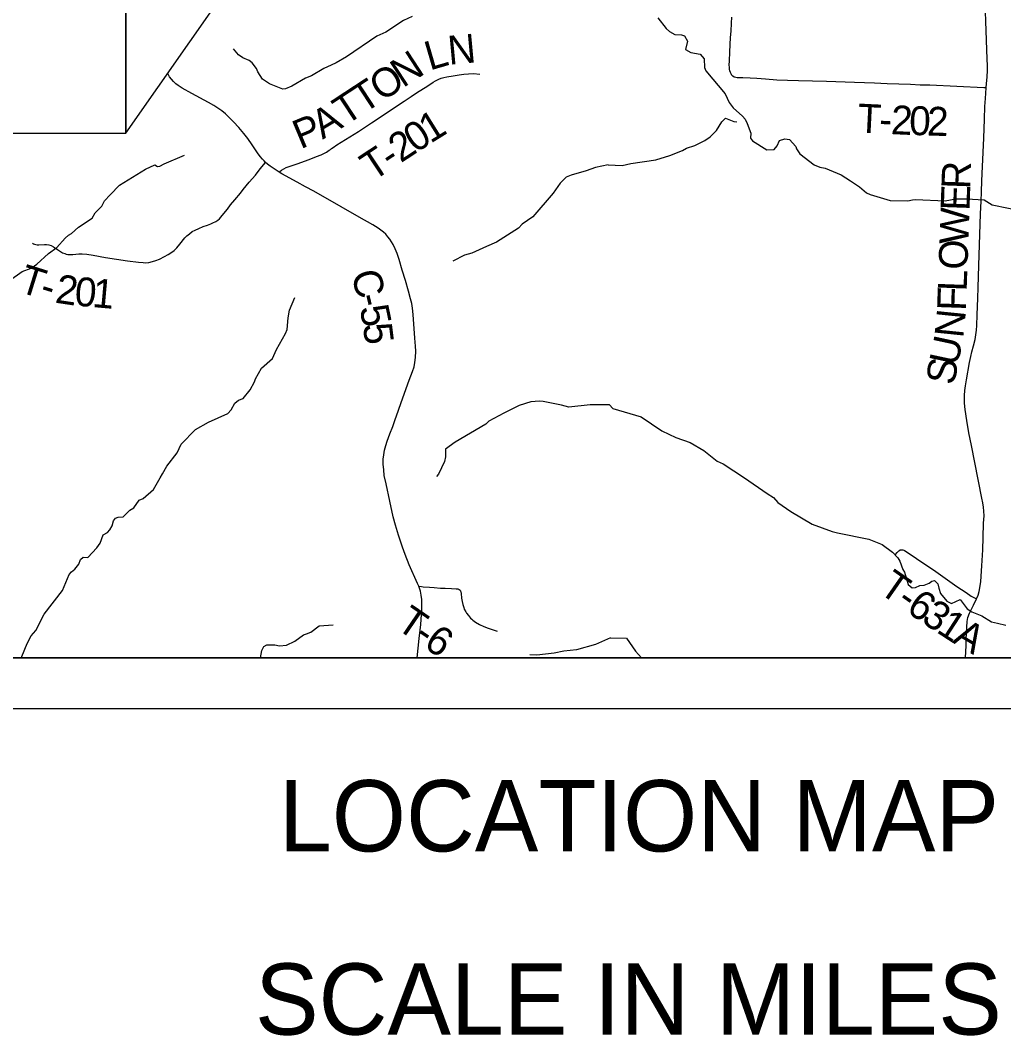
# Model space of a CAD drawing. Extents: x 0 to 34, y 0 to 22.
# Drawn here: x 26.169 to 28.101, y 13.358 to 15.353 of the extents above; entities that cross this region are included whole.
import ezdxf

# ---------------------------------------------------------------- set-up
doc = ezdxf.new("R2010")
doc.units = 0
for name, color, linetype in [('GM_X_Adjacent_County', 7, 'Continuous'), ('GM_X_County', 7, 'Continuous'), ('GM_X_County_Road', 7, 'Continuous'), ('GM_X_County_Road_Text', 7, 'Continuous'), ('GM_X_Minor_River', 7, 'Continuous'), ('GM_X_Township', 7, 'Continuous'), ('GM_X_Township_Road', 7, 'Continuous'), ('GM_X_Township_Road_Text', 7, 'Continuous'), ('SH_Data', 7, 'Continuous'), ('SH_Text', 7, 'Continuous')]:
    doc.layers.add(name, color=color, linetype=linetype)

msp = doc.modelspace()

# ---------------------------------------------------------------- linework, layer by layer
at = {"layer": 'GM_X_Adjacent_County'}
msp.add_lwpolyline([(28.7526, 20.9), (24.0167, 20.9), (24.0167, 14.1), (28.5181, 14.1)], dxfattribs=at)
at = {"layer": 'GM_X_County'}
msp.add_lwpolyline([(28.7526, 20.9), (24.0167, 20.9), (24.0167, 14.1), (28.5181, 14.1)], dxfattribs=at)
at = {"layer": 'GM_X_County_Road'}
for points in [[(28.0665, 15.2197), (28.0671, 15.2285), (28.0682, 15.241), (28.0688, 15.2543), (28.0688, 15.2639), (28.0682, 15.2763), (28.066, 15.3505), (28.0651, 15.3691)], [(26.651, 15.073), (26.6481, 15.0762), (26.6446, 15.08), (26.6406, 15.0849), (26.6352, 15.0923), (26.6248, 15.1076), (26.6158, 15.1202), (26.6081, 15.1299), (26.5981, 15.1417), (26.5877, 15.1533), (26.579, 15.1622), (26.5722, 15.1685), (26.5649, 15.1745), (26.5573, 15.1799), (26.5494, 15.1849), (26.5386, 15.1911), (26.5059, 15.2087), (26.487, 15.2193), (26.4793, 15.2242), (26.4744, 15.2279), (26.4699, 15.2321), (26.466, 15.2367), (26.4625, 15.2417), (26.4594, 15.247), (26.4588, 15.2483)], [(28.0475, 14.2159), (28.0507, 14.2234), (28.0529, 14.2307), (28.0542, 14.238), (28.0557, 14.2503), (28.058, 14.2812), (28.0597, 14.3121), (28.0608, 14.3369), (28.0615, 14.365), (28.0623, 14.3793), (28.062, 14.3885), (28.0615, 14.396), (28.0599, 14.4049), (28.0581, 14.4139), (28.0443, 14.4841), (28.0374, 14.5176), (28.0326, 14.542), (28.0284, 14.5664), (28.0254, 14.5879), (28.0241, 14.6003), (28.0238, 14.6096), (28.0239, 14.6158), (28.0247, 14.6251), (28.026, 14.6343), (28.0281, 14.6465), (28.0338, 14.6802), (28.0362, 14.6924), (28.0384, 14.7015), (28.0415, 14.7134), (28.0445, 14.7255), (28.046, 14.7347), (28.0472, 14.7439), (28.0479, 14.7532), (28.0485, 14.7741), (28.0499, 14.8068), (28.0509, 14.8275), (28.0523, 14.8712), (28.0555, 14.9723), (28.0564, 14.9971), (28.0571, 15.0157), (28.058, 15.0375), (28.0592, 15.0654), (28.0618, 15.1212), (28.0631, 15.1584), (28.0639, 15.1831), (28.0649, 15.1986), (28.0665, 15.2197)], [(26.6778, 15.0544), (26.6699, 15.0592), (26.6597, 15.0662), (26.655, 15.0697), (26.651, 15.073)], [(26.9518, 14.2408), (26.9495, 14.246), (26.9333, 14.283), (26.925, 14.3031), (26.9196, 14.3176), (26.9119, 14.3412), (26.9061, 14.3609), (26.9018, 14.3771), (26.8948, 14.4078), (26.8875, 14.4423), (26.8842, 14.4583), (26.8829, 14.4696), (26.8819, 14.4805), (26.8821, 14.4903), (26.8829, 14.4989), (26.8847, 14.508), (26.8871, 14.517), (26.8899, 14.5258), (26.8951, 14.5404), (26.9006, 14.5549), (26.9049, 14.5665), (26.9123, 14.587), (26.9175, 14.6017), (26.9332, 14.6455), (26.9398, 14.663), (26.9428, 14.6721), (26.9444, 14.6802), (26.9457, 14.6902), (26.946, 14.7023), (26.9454, 14.7126), (26.9444, 14.7281), (26.9408, 14.7746), (26.9395, 14.787), (26.9379, 14.7962), (26.9359, 14.8053), (26.9319, 14.8204), (26.9256, 14.8412), (26.9193, 14.862), (26.9131, 14.8828), (26.9091, 14.8947), (26.9056, 14.9034), (26.9017, 14.9119), (26.8986, 14.9174), (26.8951, 14.9226), (26.8912, 14.9275), (26.887, 14.9322), (26.8824, 14.9365), (26.8775, 14.9404), (26.8724, 14.9441), (26.8618, 14.9506), (26.8348, 14.966), (26.7997, 14.986), (26.7457, 15.0167), (26.7293, 15.0256), (26.7129, 15.0345), (26.6831, 15.0511), (26.6778, 15.0544)], [(26.9484, 14.1), (26.9529, 14.1381), (26.9556, 14.166), (26.9581, 14.1953), (26.9581, 14.2058), (26.9579, 14.215), (26.9568, 14.2236), (26.955, 14.2309), (26.9532, 14.2371), (26.9518, 14.2408)], [(28.0256, 14.1), (28.0269, 14.1246), (28.0271, 14.137), (28.0289, 14.1714), (28.0307, 14.1794), (28.034, 14.1878), (28.0369, 14.1946), (28.0418, 14.204), (28.0475, 14.2159)]]:
    msp.add_lwpolyline(points, dxfattribs=at)
at = {"layer": 'GM_X_Minor_River'}
for points in [[(26.9391, 15.3603), (26.9217, 15.3522), (26.887, 15.3289), (26.8696, 15.3212), (26.8101, 15.2806), (26.7897, 15.2687), (26.7799, 15.2641), (26.7655, 15.258), (26.7414, 15.2434), (26.7293, 15.2388), (26.7025, 15.2234), (26.69, 15.218), (26.6847, 15.2172), (26.6585, 15.2277), (26.6452, 15.2367), (26.636, 15.2511), (26.6333, 15.2579), (26.6249, 15.2692), (26.6184, 15.2737), (26.6063, 15.2786), (26.5975, 15.285), (26.5876, 15.2967)], [(27.4212, 15.3576), (27.4377, 15.3365), (27.4441, 15.3305), (27.4548, 15.3245), (27.4681, 15.3242), (27.4738, 15.3223), (27.4799, 15.3113), (27.4755, 15.295), (27.4865, 15.289), (27.5044, 15.2857), (27.5124, 15.2767), (27.5133, 15.26), (27.516, 15.2535), (27.5535, 15.2079), (27.5615, 15.1912), (27.5692, 15.1803), (27.5875, 15.1644), (27.5929, 15.1584), (27.5971, 15.1497), (27.6041, 15.1311), (27.6034, 15.1209), (27.6076, 15.116), (27.6354, 15.0983), (27.6502, 15.0988), (27.6558, 15.1061), (27.6606, 15.1167), (27.6712, 15.1195), (27.6799, 15.1184), (27.6926, 15.1048), (27.6941, 15.0999), (27.7006, 15.0905), (27.7288, 15.0686), (27.7399, 15.0642), (27.7501, 15.0623), (27.7817, 15.0489), (27.7999, 15.0369), (27.8175, 15.0256), (27.8312, 15.0136), (27.8384, 15.0102), (27.8779, 14.9987), (27.9128, 14.9982), (27.9219, 14.9998), (27.9279, 15.0006), (27.9859, 14.998), (28.0067, 15.0019), (28.0276, 15.0017), (28.0624, 14.9996), (28.078, 14.9903), (28.1426, 14.9771)], [(27.3236, 15.0684), (27.3511, 15.0671), (27.3681, 15.0714), (27.4177, 15.0786), (27.4453, 15.0871), (27.4698, 15.0968), (27.4777, 15.1014), (27.494, 15.1068), (27.514, 15.1161), (27.5242, 15.1234), (27.5366, 15.136), (27.5471, 15.1531), (27.5546, 15.1604), (27.5709, 15.1537), (27.5766, 15.153)], [(26.1479, 14.8417), (26.1728, 14.8589), (26.1902, 14.8659), (26.2018, 14.8732), (26.2244, 14.8942), (26.241, 14.9064), (26.2572, 14.9247), (26.264, 14.9305), (26.2696, 14.9335), (26.2835, 14.9461), (26.3103, 14.9638), (26.3159, 14.9744), (26.3291, 14.9874), (26.3347, 14.9981), (26.3456, 15.0099), (26.3637, 15.029), (26.415, 15.0604), (26.4335, 15.0685), (26.4384, 15.0651), (26.4433, 15.0659), (26.452, 15.0705), (26.4917, 15.0874)], [(27.3236, 15.0684), (27.299, 15.0633), (27.2808, 15.0567), (27.251, 15.0486), (27.2415, 15.0443), (27.2295, 15.0329), (27.2156, 15.0131), (27.1761, 14.9665), (27.155, 14.952), (27.1475, 14.944), (27.1045, 14.9168), (27.0849, 14.9079), (27.0562, 14.8952), (27.0414, 14.891), (27.0188, 14.8791)], [(26.1716, 14.1), (26.1719, 14.1028), (26.1823, 14.1286), (26.1905, 14.1435), (26.1995, 14.1542), (26.216, 14.1858), (26.252, 14.2327), (26.2651, 14.2642), (26.27, 14.2692), (26.2764, 14.2746), (26.2839, 14.2845), (26.2872, 14.2932), (26.2925, 14.2978), (26.3016, 14.2971), (26.3192, 14.3162), (26.326, 14.3257), (26.3316, 14.3417), (26.3402, 14.3467), (26.3451, 14.3516), (26.3493, 14.3593), (26.3522, 14.3691), (26.3563, 14.3745), (26.3613, 14.3764), (26.3711, 14.3772), (26.3843, 14.3902), (26.3918, 14.3948), (26.4023, 14.4097), (26.4102, 14.4131), (26.4306, 14.4311), (26.4441, 14.4536), (26.4482, 14.4619), (26.4572, 14.4764), (26.4774, 14.5027), (26.4849, 14.5198), (26.5131, 14.5485), (26.5388, 14.5634), (26.5765, 14.5804), (26.5833, 14.5872), (26.5908, 14.6002), (26.5976, 14.6063), (26.6066, 14.6094), (26.6205, 14.6266), (26.6291, 14.6425), (26.6314, 14.6482), (26.6426, 14.6692), (26.6648, 14.6883), (26.6722, 14.7058), (26.6898, 14.7374), (26.6932, 14.7454), (26.6953, 14.7678), (26.6982, 14.783), (26.7087, 14.8081)], [(27.3328, 14.5901), (27.3263, 14.5972), (27.2885, 14.597), (27.2465, 14.5926), (27.232, 14.5963), (27.196, 14.604), (27.1888, 14.6047), (27.1722, 14.6031), (27.1491, 14.5957), (27.1189, 14.5808), (27.0895, 14.565), (27.0838, 14.5589), (27.0231, 14.5236), (27.0046, 14.5102), (27.0043, 14.495), (27.0021, 14.4859), (26.9905, 14.4612), (26.9864, 14.4562)], [(27.3328, 14.5901), (27.389, 14.5738), (27.429, 14.546), (27.4571, 14.5329), (27.4848, 14.5232), (27.5115, 14.5078), (27.5382, 14.4867), (27.5496, 14.4811), (27.5919, 14.4541), (27.6361, 14.4229), (27.6486, 14.415), (27.6574, 14.4056), (27.6826, 14.3879), (27.7244, 14.3631), (27.764, 14.3482), (27.7742, 14.346), (27.8357, 14.3332), (27.8619, 14.3231), (27.8825, 14.3077), (27.8928, 14.2964), (27.897, 14.2899), (27.9025, 14.2737), (27.9059, 14.2684), (27.9133, 14.2445), (27.9209, 14.2377), (27.9274, 14.2381), (27.9361, 14.242), (27.9444, 14.2428), (27.9546, 14.2467), (27.9599, 14.2509), (27.9648, 14.2521), (27.9713, 14.2453), (27.9736, 14.2373), (27.9767, 14.2267), (27.9894, 14.2116), (27.9985, 14.2067), (28.0151, 14.2148), (28.0293, 14.1967), (28.038, 14.1903), (28.0582, 14.1829), (28.0772, 14.1708), (28.0886, 14.1683), (28.1049, 14.1646)], [(26.6408, 14.1), (26.6433, 14.1145), (26.6478, 14.1225), (26.6535, 14.1255), (26.669, 14.1256), (26.6781, 14.1238), (26.6917, 14.125), (26.7087, 14.1331), (26.7257, 14.1457), (26.7314, 14.1473), (26.7397, 14.1504), (26.7562, 14.163), (26.7839, 14.1651)], [(27.3283, 14.1396), (27.2993, 14.1262), (27.2615, 14.1161), (27.2369, 14.1136), (27.2176, 14.1094), (27.1835, 14.1057), (27.1702, 14.106)], [(27.3283, 14.1396), (27.3601, 14.1388), (27.3778, 14.1131), (27.3893, 14.1)]]:
    msp.add_lwpolyline(points, dxfattribs=at)
at = {"layer": 'GM_X_Township'}
msp.add_lwpolyline([(24.0167, 18.4402), (24.0167, 14.1), (28.5181, 14.1)], dxfattribs=at)
at = {"layer": 'GM_X_Township_Road'}
for points in [[(27.5664, 15.2456), (27.5662, 15.2458), (27.5654, 15.2471), (27.5641, 15.2499), (27.5631, 15.2534), (27.5625, 15.2564), (27.5621, 15.2598), (27.5619, 15.2649), (27.562, 15.2723), (27.5628, 15.2909), (27.5645, 15.3188), (27.5652, 15.3312), (27.5661, 15.3466), (27.5669, 15.359)], [(26.6778, 15.0544), (26.6789, 15.0554), (26.6823, 15.0582), (26.6865, 15.061), (26.6912, 15.0634), (26.7015, 15.0668), (26.7132, 15.0708), (26.7366, 15.0793), (26.7511, 15.0847), (26.7598, 15.088), (26.7654, 15.0907), (26.7708, 15.0937), (26.7759, 15.0972), (26.7784, 15.0989), (26.7807, 15.1006), (26.7838, 15.1028), (26.7911, 15.1078), (26.8333, 15.1341), (26.8592, 15.1512), (26.9229, 15.1936), (26.9366, 15.2031), (26.9496, 15.2115), (26.9679, 15.2227), (26.9801, 15.2308), (26.9849, 15.2339), (26.991, 15.2371), (26.9959, 15.239), (27.0008, 15.2404), (27.0069, 15.2418), (27.0191, 15.2436), (27.0313, 15.2453), (27.0405, 15.2465), (27.0498, 15.2475), (27.0591, 15.2479), (27.0716, 15.2467)], [(28.0665, 15.2197), (28.062, 15.2199), (27.9556, 15.2249), (27.9463, 15.2249), (27.937, 15.2252), (27.918, 15.2263), (27.8719, 15.228), (27.847, 15.2288), (27.8075, 15.2301), (27.7529, 15.2321), (27.6975, 15.2338), (27.6761, 15.2343), (27.6549, 15.2352), (27.6332, 15.237), (27.6157, 15.2381), (27.6026, 15.2391), (27.5887, 15.2394), (27.5819, 15.2394), (27.5774, 15.2393), (27.5745, 15.2399), (27.5715, 15.2411), (27.5691, 15.2426), (27.567, 15.2447), (27.5664, 15.2456)], [(26.1933, 14.9148), (26.195, 14.9136), (26.197, 14.9127), (26.1994, 14.9119), (26.2021, 14.9115), (26.2055, 14.9113), (26.2165, 14.912), (26.2207, 14.9123), (26.2252, 14.9115), (26.2296, 14.9099), (26.234, 14.9078), (26.2384, 14.9051), (26.2419, 14.9025), (26.2478, 14.8985), (26.2522, 14.8959), (26.2565, 14.8942), (26.2593, 14.8932), (26.2625, 14.8926), (26.2659, 14.8924), (26.272, 14.8927), (26.2781, 14.8934), (26.2843, 14.8938), (26.2905, 14.8937), (26.2998, 14.8929), (26.3121, 14.8911), (26.3365, 14.8867), (26.358, 14.8832), (26.3795, 14.8802), (26.4011, 14.8775), (26.4103, 14.8765), (26.4153, 14.8762), (26.4213, 14.8767), (26.4286, 14.8786), (26.4354, 14.8807), (26.4423, 14.8834), (26.4523, 14.8886), (26.4597, 14.8926), (26.4647, 14.8956), (26.4711, 14.9003), (26.4763, 14.9053), (26.4828, 14.913), (26.4926, 14.9252), (26.4964, 14.9293), (26.5012, 14.9333), (26.5069, 14.9375), (26.5126, 14.9405), (26.5195, 14.9437), (26.5285, 14.9472), (26.5369, 14.9502), (26.5436, 14.9527), (26.5476, 14.9546), (26.553, 14.9574), (26.5572, 14.9601), (26.5602, 14.9626), (26.5659, 14.9688), (26.5759, 14.9815), (26.5823, 14.9899), (26.5907, 14.9998), (26.6014, 15.0128), (26.6071, 15.0202), (26.619, 15.0344), (26.6308, 15.0486), (26.6405, 15.0605), (26.651, 15.073)], [(27.8884, 14.3033), (27.8918, 14.307), (27.895, 14.3103), (27.8967, 14.3118), (27.8978, 14.3123), (27.899, 14.3126), (27.9003, 14.3127), (27.9018, 14.3126), (27.903, 14.3124), (27.9047, 14.3119), (27.9062, 14.3113), (27.9115, 14.3081), (27.9294, 14.2955), (27.9501, 14.2816), (27.9631, 14.273), (28.0089, 14.2406), (28.0269, 14.2283), (28.037, 14.2215), (28.0475, 14.2159)], [(26.9518, 14.2408), (26.9573, 14.2402), (26.9604, 14.2399), (26.9728, 14.2389), (26.9821, 14.2382), (26.9945, 14.2373), (27.0037, 14.2368), (27.0161, 14.2364), (27.0254, 14.236), (27.0285, 14.2356), (27.031, 14.2346), (27.0329, 14.2331), (27.0339, 14.2315), (27.0344, 14.2296), (27.035, 14.2264), (27.036, 14.2172), (27.037, 14.211), (27.0384, 14.205), (27.0401, 14.199), (27.0413, 14.1961), (27.0442, 14.1906), (27.0459, 14.188), (27.0496, 14.1831), (27.0536, 14.1783), (27.0558, 14.1761), (27.0582, 14.1741), (27.0633, 14.1705), (27.0714, 14.1659), (27.0797, 14.1617), (27.0884, 14.1583), (27.1061, 14.1523)]]:
    msp.add_lwpolyline(points, dxfattribs=at)
at = {"layer": 'SH_Data'}
for points in [[(23.9167, 21), (30.9167, 21), (30.9167, 14), (23.9167, 14)], [(24.0167, 20.9), (30.8167, 20.9), (30.8167, 14.1), (24.0167, 14.1)]]:
    msp.add_lwpolyline(points, close=True, dxfattribs=at)
at = {"layer": 'SH_Text'}
for points in [[(27.2563, 16.3872), (26.3766, 15.621), (26.3766, 15.131)], [(24.6207, 15.131), (26.3766, 15.131), (26.3766, 15.621), (24.6207, 15.621)]]:
    msp.add_lwpolyline(points, close=True, dxfattribs=at)

# ---------------------------------------------------------------- texts
at = {"layer": 'GM_X_County_Road_Text'}
for s, rotation, p in [('R', 87.9769, (28.0351, 15.0202)), ('E', 87.9768, (28.0336, 14.9777)), ('W', 87.9824, (28.0313, 14.9119)), ('O', 87.9808, (28.0295, 14.8619)), ('C', 283.7608, (26.8189, 14.8556)), ('L', 87.9768, (28.028, 14.8194)), ('F', 88.0933, (28.0267, 14.7812)), ('-', 283.2468, (26.8299, 14.8104)), ('5', 281.611, (26.8352, 14.7881)), ('N', 84.1536, (28.0213, 14.7272)), ('5', 277.0637, (26.842, 14.755)), ('U', 77.9264, (28.0098, 14.6716)), ('S', 81.1462, (28.0041, 14.6346))]:
    msp.add_text(s, height=0.0568, rotation=rotation, dxfattribs=at).set_placement(p)
at = {"layer": 'GM_X_Township_Road_Text'}
for s, rotation, p in [('N', 5.2785, (27.0114, 15.265)), ('L', 16.2551, (26.9734, 15.2537)), ('N', 33.1415, (26.9207, 15.2189)), ('O', 33.2496, (26.8789, 15.1915)), ('T', 33.2503, (26.8434, 15.1682)), ('T', 33.2921, (26.8079, 15.1449)), ('A', 31.0094, (26.7629, 15.1178)), ('T', 357.2219, (27.8127, 15.1323)), ('2', 357.3073, (27.8785, 15.1291)), ('0', 358.2135, (27.9145, 15.1275)), ('2', 358.1054, (27.9494, 15.1264)), ('P', 22.6476, (26.7195, 15.099)), ('1', 31.9392, (26.9747, 15.1097)), ('0', 33.0911, (26.9457, 15.0907)), ('-', 357.23, (27.8552, 15.1303)), ('2', 33.3769, (26.9165, 15.0715)), ('T', 33.4547, (26.8616, 15.0352)), ('-', 33.4454, (26.897, 15.0587)), ('T', 342.6899, (26.1638, 14.8197)), ('2', 351.4815, (26.2359, 14.7981)), ('0', 355.0013, (26.2743, 14.7924)), ('1', 355.0013, (26.3092, 14.7894)), ('-', 342.869, (26.2046, 14.807)), ('T', 325.1379, (27.8529, 14.2299)), ('-', 325.1936, (27.8878, 14.2055)), ('6', 325.438, (27.9072, 14.1921)), ('T', 325.6835, (26.9049, 14.1594)), ('3', 326.1285, (27.9366, 14.1718)), ('1', 326.9998, (27.9665, 14.1518)), ('6', 325.7614, (26.9593, 14.1223)), ('A', 329.6016, (27.9982, 14.1312)), ('-', 325.6985, (26.94, 14.1355))]:
    msp.add_text(s, height=0.0568, rotation=rotation, dxfattribs=at).set_placement(p)
at = {"layer": 'SH_Text'}
for s, p in [('LOCATION MAP', (26.677, 13.72)), ('SCALE IN MILES', (26.6302, 13.36))]:
    msp.add_text(s, height=0.14, dxfattribs=at).set_placement(p)

doc.saveas('drawing.dxf')
